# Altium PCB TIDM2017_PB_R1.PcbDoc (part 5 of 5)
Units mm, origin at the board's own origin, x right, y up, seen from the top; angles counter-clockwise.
Board outline 120 x 147.5 mm, 4 copper layers (Top Layer, L2, L3, Bottom Layer), stack 1.413 mm thick; 117 components, 53 nets, 3137 pads, 96 vias.
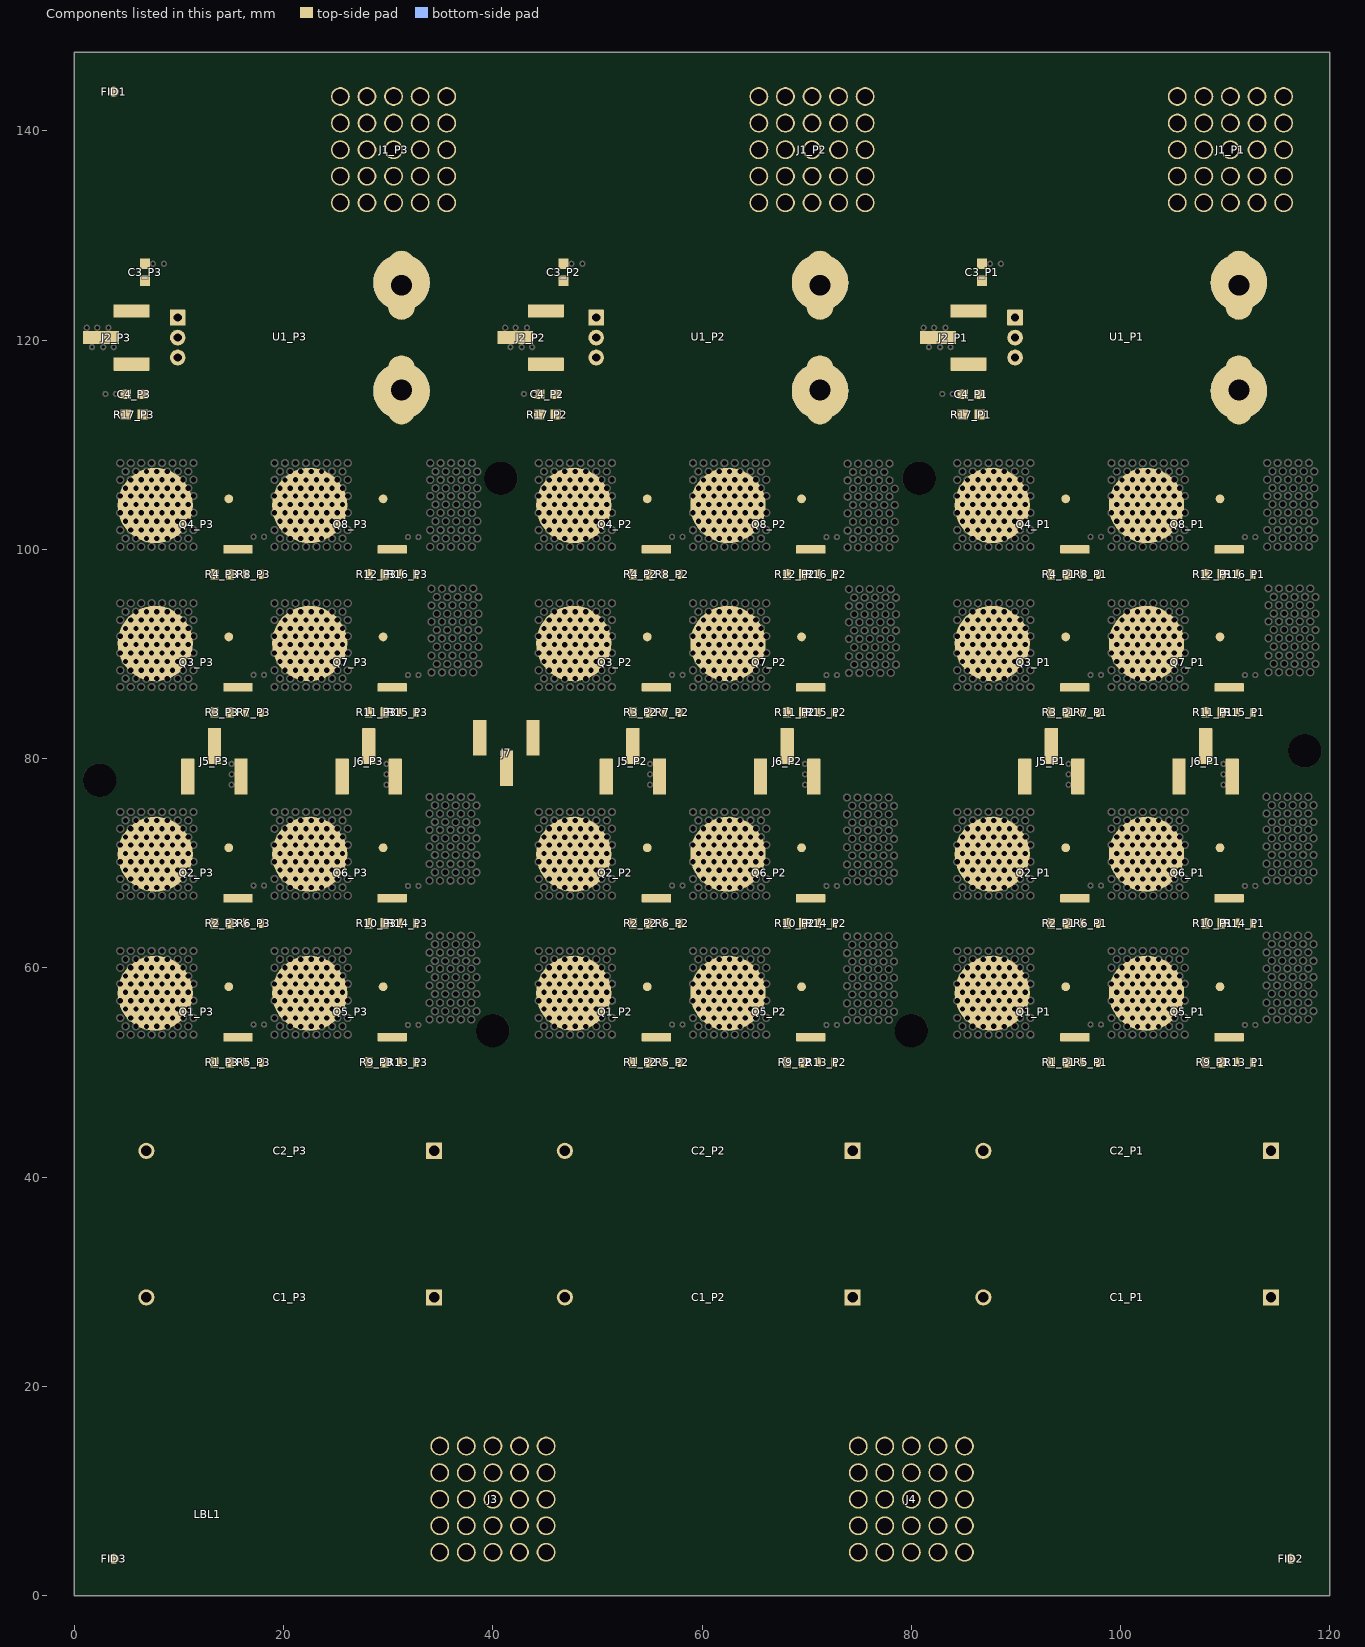
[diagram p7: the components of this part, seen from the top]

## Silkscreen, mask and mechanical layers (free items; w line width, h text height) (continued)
M10 Fab Notes:
  drawing of 189 lines, arcs and shapes, not listed
  text "DESIGN INFORMATION" at 314.503,161.447 h1.52
  text "MIN. TRACK WIDTH:" at 298.131,158.091 h1.52
  text "8" at 325.976,158.091 h1.52
  text "MIL" at 329.907,158.091 h1.52
  text "7.874" at 321.75,155 h1.52
  text "MIN. CLEARANCE:" at 298.131,154.938 h1.52
  text "MIL" at 329.907,154.938 h1.52
  text "MIN. VIA PAD SIZE:" at 298.131,151.785 h1.52
  text "24" at 325.214,151.785 h1.52
  text "MIL" at 329.907,151.785 h1.52
  text "0.05mm (2MIL)" at 315.784,148.486 h1.52
  text "MINIMUM ANNULAR RING" at 289.769,148.277 h1.52
  text "EXTERNAL" at 333.768,148.277 h1.52
  text "PER" at 294.849,145.48 h1.52
  text "IPC-D-275 CLASS 2 LEVEL C" at 300.437,145.48 h1.52
  text "MIL, HOLES" at 338.238,142.928 h1.52
  text "+/-" at 328.27,142.709 h1.52
  text "+/-" at 349.961,142.709 h1.52
  text "REGISTRATION TOLERANCES:" at 289.769,142.682 h1.52
  text "METAL" at 320.243,142.682 h1.52
  text "5" at 334.879,142.683 h1.52
  text "3" at 356.037,142.683 h1.52
  text "MIL" at 358.99,142.682 h1.52
  text "HOLE SIZE TOLERANCE (UNLESS OTHERWISE SPECIFIED):" at 289.769,140.185 h1.52
  text "+/-" at 349.961,140.112 h1.52
  text "3" at 356.037,140.085 h1.52
  text "MIL" at 358.99,140.085 h1.52
  text "MATERIAL:" at 287.87,136.589 h1.52
  text "FR-4 High Tg" at 312.926,133.324 h1.52
  text "X" at 309.257,133.122 h1.52
  text "FR-4" at 298.563,133.007 h1.52
  text "OTHER" at 336.358,133.007 h1.52
  text "62 MIL (1.6mm) +/-10%" at 306.694,129.374 h1.52
  text "X" at 303.643,129.312 h1.52
  text "THICKNESS:" at 289.769,129.165 h1.52
  text "OTHER" at 339.33,129.165 h1.52
  text "TOLERANCE:" at 289.769,125.652 h1.52
  text "X" at 311.314,125.652 h1.52
  text "ANSI IPC-6012 TYPE 3 CLASS 2" at 315.836,125.652 h1.52
  text "OTHER +/-" at 315.835,121.989 h1.52
  text "BOW & TWIST:" at 289.769,118.302 h1.52
  text "X" at 311.314,118.302 h1.52
  text "ANSI IPC-6012 TYPE 3 CLASS 2" at 315.836,118.302 h1.52
  text "OTHER +/-" at 315.835,114.576 h1.52
  text "DRILLING:" at 287.87,111.258 h1.52
  text "NC_DRILL FILES" at 332.599,108.586 h1.52
  text "REFERENCE:" at 289.769,108.486 h1.52
  text "X" at 306.463,108.484 h1.52
  text "AS SHOWN" at 310.984,108.486 h1.52
  text "X" at 329.348,108.486 h1.52
  text "OTHER" at 340.168,104.873 h1.52
  text "PTH COPPER THICKNESS:" at 289.761,104.783 h1.52
  text "X" at 318.697,104.783 h1.52
  text "20-30 um" at 321.948,104.783 h1.52
  text "BOARD FINISH:" at 287.87,101.034 h1.52
  text "SILKSCREEN:" at 291.812,98.237 h1.52
  text "X" at 316.14,98.237 h1.52
  text "TOP" at 319.112,98.237 h1.52
  text "X" at 329.094,98.237 h1.52
  text "BOTTOM" at 332.091,98.237 h1.52
  text "SILKSCREEN COLOR:" at 291.812,94.295 h1.52
  text "X" at 316.115,94.295 h1.52
  text "WHITE" at 319.112,94.295 h1.52
  text "OTHER" at 332.091,94.295 h1.52
  text "X" at 319.442,90.652 h1.52
  text "GREEN" at 322.439,90.652 h1.52
  text "OTHER" at 338.136,90.652 h1.52
  text "SOLDER RESIST COLOR:" at 291.812,90.477 h1.52
  text "X" at 319.442,86.734 h1.52
  text "MATTE" at 322.439,86.734 h1.52
  text "SEMI-GLOSS" at 338.125,86.717 h1.52
  text "IMMERSION GOLD (ENIG)" at 314.819,82.345 h1.52
  text "ENEPIG" at 348.793,82.162 h1.52
  text "SURFACE FINISH:" at 287.87,82.136 h1.52
  text "X" at 310.298,82.136 h1.52
  text "IMM. TIN/SILVER OR EQUIV" at 296.24,78.649 h1.52
  text "OTHER" at 332.599,78.549 h1.52
  text "ARRAY/PANEL:" at 287.87,74.602 h1.52
  text "CUT AND TRIM PER M1 BOARD OUTLINE" at 314.819,74.393 h1.52
  text "N.C. ROUTE" at 314.819,70.94 h1.52
  text "X" at 332.295,70.94 h1.52
  text "V. SCORE" at 336.816,70.94 h1.52
  text "CERTIFICATION:" at 287.87,67.66 h1.52
  text "MATERIALS AND WORKMANSHIP FOR ALL PCBS" at 306.285,67.66 h1.52
  text "TO MEET OR EXCEED THE REQUIREMENTS OF:" at 306.285,65.271 h1.52
  text "X" at 297.078,62.003 h1.52
  text "ANSI IPC-A-600F CLASS ->" at 300.329,62.003 h1.52
  text "X" at 342.188,62.003 h1.52
  text "2" at 344.982,62.003 h1.52
  text "1" at 336.981,61.965 h1.52
  text "3" at 353.973,61.965 h1.52
  text "X" at 317.702,58.252 h1.52
  text "RoHS" at 320.953,58.252 h1.52
  text "OTHER" at 337.321,58.252 h1.52
  text "PER ORDER" at 347.407,58.252 h1.52
  text "ALL BOARDS MUST MEET OR EXCEED UL94-V0 REQUIREMENTS." at 288.569,54.345 h1.52
  text "PCB MUST BEAR THE UL94V-0 UL REGISTERED MATERIAL ID NUMBER" at 288.569,51.397 h1.52
  text "ADDITIONAL REQUIREMENTS:" at 287.87,47.094 h1.52
  text "MICROSECTION:" at 289.769,44.373 h1.52
  text "YES" at 312.775,44.373 h1.52
  text "REQUIRED" at 334.657,40.707 h1.52
  text "BARE BOARD ELEC. TEST:" at 289.769,40.634 h1.52
  text "NONE" at 322.935,40.634 h1.52
  text "X" at 331.66,40.634 h1.52
  text "PER ORDER" at 349.693,40.634 h1.52
  text "XX MIL VIAS REQUIRE NON-CONDUCTIVE FILL AND PLANARIZE" at 294.04,35.428 h1.5
  text "XX MIL VIAS REQUIRE CONDUCTIVE FILL AND PLANARIZE" at 294.243,32.787 h1.52
  text "OUTER XX MIL TRACES REQUIRE 50 OHM SINGLE-ENDED IMPEDANCE" at 294.218,28.637 h1.47
  text "LAYER 2 & 3 (INNER LAYERS) XX MIL WIDE, XX MIL SPACE / TRACES REQUIRE 100 OHM DIFFERENTIAL IMPEDANCE" at 294.015,22.65 h1.52
  text ".Layer_Name" at 14.656,-21.806 h1.52
M11 Gerber Information:
  lines w0.254: -7.417,-23.626 160.223,-23.626 ; -7.417,-18.462 160.274,-18.462 ; -7.417,-13.297 -7.417,-28.791 94.31,-28.791 160.274,-28.791 160.274,-13.297 -7.404,-13.297 -7.404,-28.791 32.614,-28.791 ; 55.194,-28.791 55.194,-13.297 ; 87.376,-18.462 87.376,-13.297 ; 108.712,-18.462 108.712,-13.297 ; 124.511,-28.956 124.511,-23.804
  text "ALL ARTWORK VIEWED FROM TOP SIDE" at -5.804,-16.654 h1.52
  text "BOARD #:" at 57.099,-16.654 h1.52
  text ".PRJ_Number" at 70.955,-16.654 h1.52
  text "REV:" at 92.405,-16.654 h1.52
  text ".PCB_Rev" at 99.809,-16.654 h1.52
  text "SVN REV:" at 113.69,-16.654 h1.52
  text ".VersionControl_RevNumber" at 126.543,-16.654 h1.52
  text "LAYER NAME =" at -5.804,-21.806 h1.52
  text "TID #:" at 57.099,-21.819 h1.52
  text ".TID" at 70.955,-21.819 h1.52
  text "PLOT NAME =" at -5.804,-27.034 h1.52
  text ".plot_File_Name" at 14.656,-27.034 h1.52
  text "GENERATED    :" at 57.15,-27.034 h1.52
  text ".Print_Date" at 79.235,-27.034 h1.52
  text ".Print_Time" at 97.752,-27.034 h1.52
  text "TEXAS INSTRUMENTS" at 129.87,-27.034 h1.52
M12 Stackup:
  drawing of 295 lines, arcs and shapes, not listed
  text "Layer" at 249.469,200.023 h1.52
  text "Name" at 259.88,200.023 h1.52
  text "Material" at 283.496,200.023 h1.52
  text "Thickness" at 305.334,200.023 h1.52
  text "Constant" at 321.84,200.023 h1.52
  text "Board Layer Stack" at 336.314,200.023 h1.52
  text "Top Overlay" at 259.88,196.975 h1.52
  text "Top Solder" at 259.88,193.927 h1.52
  text "Solder Resist" at 283.496,193.927 h1.52
  text "0.40mil" at 305.334,193.927 h1.52
  text "3.5" at 321.84,193.927 h1.52
  text "1" at 249.469,190.879 h1.52
  text "Top Layer" at 259.88,190.879 h1.52
  text "CF-004" at 283.496,190.879 h1.52
  text "2.76mil" at 305.334,190.879 h1.52
  text "Dielectric 1" at 259.88,187.831 h1.52
  text "PP-006" at 283.496,187.831 h1.52
  text "2.80mil" at 305.334,187.831 h1.52
  text "4.1" at 321.84,187.831 h1.52
  text "2" at 249.469,184.783 h1.52
  text "L2" at 259.88,184.783 h1.52
  text "2.76mil" at 305.334,184.783 h1.52
  text "Dielectric1" at 259.88,181.735 h1.52
  text "FR-4 High Tg" at 283.496,181.735 h1.52
  text "39.00mil" at 305.334,181.735 h1.52
  text "4.8" at 321.84,181.735 h1.52
  text "3" at 249.469,178.687 h1.52
  text "L3" at 259.88,178.687 h1.52
  text "2.76mil" at 305.334,178.687 h1.52
  text "Dielectric 2" at 259.88,175.639 h1.52
  text "PP-006" at 283.496,175.639 h1.52
  text "2.80mil" at 305.334,175.639 h1.52
  text "4.1" at 321.84,175.639 h1.52
  text "4" at 249.469,172.591 h1.52
  text "Bottom Layer" at 259.88,172.591 h1.52
  text "CF-004" at 283.496,172.591 h1.52
  text "2.76mil" at 305.334,172.591 h1.52
  text "Bottom Solder" at 259.88,169.543 h1.52
  text "Solder Resist" at 283.496,169.543 h1.52
  text "0.40mil" at 305.334,169.543 h1.52
  text "3.5" at 321.84,169.543 h1.52
  text "Bottom Overlay" at 259.88,166.495 h1.52
  text ".Layer_Name" at 14.656,-21.806 h1.52
M13 Component Bodies Top:
  text ".Layer_Name" at 14.656,-21.806 h1.52
M14 Component Bodies Bottom:
  text ".Layer_Name" at 14.656,-21.806 h1.52
M15 Courtyards Top:
  text ".Layer_Name" at 14.656,-21.806 h1.52
M16 Courtyards Bottom:
  text ".Layer_Name" at 14.656,-21.806 h1.52
Drill Drawing:
  circle w0.254: c136.238,83.573 r0.702
  lines w0.254: 135.537,63.925 136.238,64.276 136.94,63.925 136.589,64.627 136.94,65.329 136.238,64.978 135.537,65.329 135.888,64.627 135.537,63.925 ; 135.537,67.083 136.94,67.083 136.94,68.486 135.537,68.486 135.537,67.083 ; 135.537,71.644 136.94,71.644 136.238,70.241 135.537,71.644 ; 135.537,73.749 135.888,73.749 136.238,73.398 136.589,73.749 136.94,73.749 136.589,74.1 136.94,74.451 136.589,74.451 136.238,74.802 135.888,74.451 135.537,74.451 135.888,74.1 135.537,73.749 ; 135.537,76.907 135.888,76.907 135.888,76.556 136.589,76.556 136.589,76.907 136.94,76.907 136.94,77.609 136.589,77.609 136.589,77.959 135.888,77.959 135.888,77.609 135.537,77.609 135.537,76.907 ; 135.537,80.415 136.238,79.714 136.94,80.415 136.238,81.117 135.537,80.415
  lines w0.305: 134.264,62.978 216.344,62.978 ; 134.264,85.082 216.344,85.082 ; 142.846,59.82 142.846,88.24 ; 151.279,59.82 151.279,88.24 ; 167.448,59.82 167.448,88.24 ; 174.03,59.82 174.03,88.24 ; 183.559,59.82 183.559,88.24 ; 201.957,59.82 201.957,88.24 ; 134.264,59.82 216.344,59.82 216.344,88.24 134.264,88.24 134.264,59.82
  text "Symbol" at 136.159,86.029 h1.83
  text "Quantity" at 143.793,86.029 h1.83
  text "Finished Hole Size" at 152.226,86.029 h1.83
  text "Plated" at 168.395,86.029 h1.83
  text "Hole Type" at 174.977,86.029 h1.83
  text "Drill Layer Pair" at 184.506,86.029 h1.83
  text "Hole Tolerance" at 202.904,86.029 h1.83
  text "6" at 143.793,82.871 h1.52
  text "125.98mil (3.200mm)" at 152.226,82.871 h1.52
  text "NPTH" at 168.395,82.871 h1.52
  text "Round" at 174.977,82.871 h1.52
  text "Top Layer - Bottom Layer" at 184.506,82.871 h1.52
  text "96" at 143.793,79.714 h1.52
  text "11.81mil (0.300mm)" at 152.226,79.714 h1.52
  text "PTH" at 168.395,79.714 h1.52
  text "Round" at 174.977,79.714 h1.52
  text "Top Layer - Bottom Layer" at 184.506,79.714 h1.52
  text "2747" at 143.793,76.556 h1.52
  text "19.69mil (0.500mm)" at 152.226,76.556 h1.52
  text "PTH" at 168.395,76.556 h1.52
  text "Round" at 174.977,76.556 h1.52
  text "Top Layer - Bottom Layer" at 184.506,76.556 h1.52
  text "9" at 143.793,73.398 h1.52
  text "31.50mil (0.800mm)" at 152.226,73.398 h1.52
  text "PTH" at 168.395,73.398 h1.52
  text "Round" at 174.977,73.398 h1.52
  text "Top Layer - Bottom Layer" at 184.506,73.398 h1.52
  text "12" at 143.793,70.241 h1.52
  text "39.37mil (1.000mm)" at 152.226,70.241 h1.52
  text "PTH" at 168.395,70.241 h1.52
  text "Round" at 174.977,70.241 h1.52
  text "Top Layer - Bottom Layer" at 184.506,70.241 h1.52
  text "125" at 143.793,67.083 h1.52
  text "58.07mil (1.475mm)" at 152.226,67.083 h1.52
  text "PTH" at 168.395,67.083 h1.52
  text "Round" at 174.977,67.083 h1.52
  text "Top Layer - Bottom Layer" at 184.506,67.083 h1.52
  text "6" at 143.793,63.925 h1.52
  text "78.74mil (2.000mm)" at 152.226,63.925 h1.52
  text "PTH" at 168.395,63.925 h1.52
  text "Slot" at 174.977,63.925 h1.52
  text "Top Layer - Bottom Layer" at 184.506,63.925 h1.52
  text "3001 Total" at 143.793,60.767 h1.52
  text "Slot definitions :" at 136.159,58.557 h1.52
  text "Routed Path Length" at 147.607,58.557 h1.52
  text "= Calculated from tool start centre position to tool end centre position." at 161.317,58.557 h1.52
  text "Hole Length" at 147.607,57.294 h1.52
  text "= Routed Path Length + Tool Size = Slot length as defined in the PCB layout" at 156.242,57.294 h1.52
  text ".Layer_Name" at 14.656,-21.806 h1.52
M17 Embedded Cavity:
  text ".Layer_Name" at 14.656,-21.806 h1.52
M18 Embedded Assembly:
  text ".Layer_Name" at 14.656,-21.806 h1.52
M19 Embedded Keepout:
  text ".Layer_Name" at 14.656,-21.806 h1.52

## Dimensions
0,147.5 to 120,147.5 on M2 Board Dimensions
0,-10.16 to 25.4,-10.16 on M2 Board Dimensions
0,0 to 120,0 on M2 Board Dimensions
